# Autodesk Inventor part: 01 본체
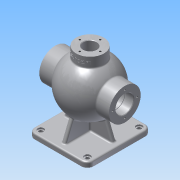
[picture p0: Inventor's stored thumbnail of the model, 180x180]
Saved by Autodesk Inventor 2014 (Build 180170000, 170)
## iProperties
Created: 2017-01
Part Number: 01 본체
Material: Aluminum 6061
Document SubType Name: Modeling
Designer: ksu
Density: 2.71 g/cm^3
Appearance: Aluminum - Flat
Author: ksu
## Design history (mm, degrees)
sketch "Sketch1"
  geometry: L1 (0, 0)-(20.642, 0); L2 (99.745, 0)-(136, 0); L3 (0, 0)-(136, 0); L4 (0, 0)-(136, 0); L5 (136, 0)-(136, 31); L6 (0, 31)-(0, 0); L7 (136, 31)-(110.741, 31); L8 (25.012, 31)-(0, 31); A1 r 53 centre (67.876, -0.171) between (110.741, 31) and (25.012, 31)
  constraints: 16 end point, 3 horizontal, 3 parallel, 2 point on circle, 1 centre point, 1 collinear, 1 perpendicular
  dimensions: "d2" = 136 distance between parallel lines of L6 L5; "d40" = 31 distance between parallel lines of L1 L8; "d41" = 31 distance between parallel lines of L2 L7
revolve "Revolution1" sketch "Sketch1" stored, may be unused: angle "d3" = 90 deg
workplane "Work Plane1"
sketch "Sketch2"
  geometry: L1 (0, 31)-(0, -31) reference; L2 (-136, 31)-(-136, -31) reference; L3 (-110.741, 31)-(-136, 31) reference; L4 (-22.5, 62.5)-(-113.5, 62.5); L5 (-125.5, 50.5)-(-125.5, -50.5); L6 (-113.5, -62.5)-(-22.5, -62.5); L7 (-10.5, -50.5)-(-10.5, 50.5); A1 r 12 centre (-22.5, 50.5) between (-10.5, 50.5) and (-22.5, 62.5); A2 r 12 centre (-22.5, -50.5) between (-22.5, -62.5) and (-10.5, -50.5); A3 r 12 centre (-113.5, -50.5) between (-125.5, -50.5) and (-113.5, -62.5); A4 r 12 centre (-113.5, 50.5) between (-113.5, 62.5) and (-125.5, 50.5); 4 further points
  constraints: 8 end point, 8 point on circle, 8 tangent, 6 point on line, 4 centre point, 3 equal radius, 2 parallel, 1 horizontal, 1 perpendicular
  dimensions: "d10" = 115 distance of point (-10.5, -62.5) point (-125.5, -62.5); "d11" = 125 distance of point (-125.5, -62.5) point (-125.5, 62.5); "d12" = 12 radius of A1
extrude "Extrusion1" join sketch "Sketch2" distance "d13" = 10; taper "d14" = 0 deg
sketch "Sketch3"
  geometry: A1 r 12 centre (113.5, -50.5) between (113.5, -62.5) and (125.5, -50.5) reference; A2 r 12 centre (113.5, 50.5) between (125.5, 50.5) and (113.5, 62.5) reference; A3 r 12 centre (22.5, 50.5) between (22.5, 62.5) and (10.5, 50.5) reference; A4 r 12 centre (22.5, -50.5) between (10.5, -50.5) and (22.5, -62.5) reference; 5 further points
  constraints: 4 coincident
hole "Hole1" sketch "Sketch3" at (22.5, -50.5), (22.5, 50.5), (113.5, 50.5), (113.5, -50.5) diameter "d15" = 8; stored, may be unused: countersink angle "d19" = 90 deg, drill point angle "d21" = 0 deg; dims "d16" = 6, "d17" = 12, "d18" = 3, "d20" = 10
workplane "Work Plane2"
workplane "Work Plane3"
workplane "Work Plane4"
sketch "Sketch10"
  geometry: C1 r 27 at (-67.876, -0.171); A1 r 53 centre (-67.876, -0.171) between (-25.012, 31) and (-110.741, 31) reference; 1 further point
  constraints: 1 centre point, 1 coincident
  dimensions: "d72" = 54 diameter of C1
extrude "Extrusion5" join sketch "Sketch10" distance "d73" = 50; taper "d74" = 0 deg
sketch "Sketch11"
  geometry: L1 (0, -31)-(0, 31) reference; L2 (0, 31)-(25.012, 31) reference; L3 (40.877, 45.436)-(40.877, 65) reference; L4 (40.877, 65)-(94.876, 65) reference; L5 (94.876, 65)-(94.876, 45.436) reference; L6 (110.741, 31)-(136, 31) reference; L7 (136, 31)-(136, -31) reference; L8 (136, -31)-(110.741, -31) reference; L9 (25.012, -31)-(0, -31) reference; L10 (10.5, -75)-(125.5, -75) reference; L11 (125.5, -75)-(125.5, -85) reference; L12 (125.5, -85)-(10.5, -85) reference; L13 (10.5, -85)-(10.5, -75) reference; L14 (0, 0)-(136, 0); L15 (136, 0)-(136, 17.5); L16 (0, 17.5)-(0, 0); L17 (28.523, 17.5)-(0, 17.5); L18 (120, 0)-(118.25, 0); L19 (118.25, 17.5)-(118.25, 18.5); L20 (118.25, 18.5)-(120, 18.5); L21 (120, 18.5)-(120, 17.5); L22 (136, 17.5)-(120, 17.5); L23 (118.25, 17.5)-(107.23, 17.5); A1 r 53 centre (67.876, -0.171) between (40.877, 45.436) and (25.012, 31) reference; A2 r 53 centre (67.876, -0.171) between (110.741, 31) and (94.876, 45.436) reference; A3 r 43 centre (67.876, 0.171) between (107.23, 17.5) and (28.523, 17.5); A4 r 53 centre (67.876, 0.171) between (25.012, -31) and (110.741, -31) reference
  constraints: 20 end point, 6 parallel, 2 horizontal, 2 perpendicular, 2 point on circle, 2 point on line, 1 centre point
  dimensions: "d75" = 86 diameter of A3; "d77" = 1.75 distance of L19.end L20.end; "d78" = 16 distance between parallel lines of L7 L21; "d79" = 18.5 distance of L20.end L18.start
revolve "Revolution2" sketch "Sketch11" stored, may be unused: angle "d80" = 90 deg
sketch "Sketch12"
  geometry: C1 r 17.5 at (0, 0) reference; 4 further points
  constraints: 5 other
  dimensions: "d81" = 24 distance of C1.centre point (0, 24); "d84" = 360 deg dimension on C1.centre point (0, 24) (derived)
hole "Hole2" sketch "Sketch12" at (0, 24), (-24, 0), (0, -24), (24, 0) diameter "d86" = 3.459; stored, may be unused: countersink angle "d90" = 90 deg, drill point angle "d92" = 118 deg; dims "d87" = 16, "d88" = 12, "d89" = 3, "d91" = 19
sketch "Sketch13"
  geometry: C1 r 17.5 at (0, 0) reference; 4 further points
  constraints: 5 other
  dimensions: "d93" = 22.5 distance of C1.centre point (0, 22.5); "d96" = 360 deg dimension on C1.centre point (0, 22.5) (derived)
hole "Hole3" sketch "Sketch13" at (0, 22.5), (-22.5, 0), (0, -22.5), (22.5, 0) diameter "d98" = 3.459; stored, may be unused: countersink angle "d102" = 90 deg, drill point angle "d104" = 118 deg; dims "d99" = 12, "d100" = 12, "d101" = 3, "d103" = 15
sketch "Sketch14"
  geometry: C1 r 27 at (0, 0) reference; C2 r 13 at (0, 0); 1 further point
  constraints: 1 centre point, 1 coincident
  dimensions: "d105" = 26 diameter of C2
extrude "Extrusion6" cut sketch "Sketch14" distance "d106" = 50; taper "d107" = 0 deg
sketch "Sketch15"
  geometry: C1 r 13 at (0, 0) reference; 5 further points
  constraints: 5 other
  dimensions: "d108" = 20 distance of C1.centre point (0, 20); "d111" = 360 deg dimension on C1.centre point (0, 20) (derived)
hole "Hole4" sketch "Sketch15" at (0, 20), (-20, 0), (0, -20), (20, 0) diameter "d113" = 3.459; stored, may be unused: countersink angle "d117" = 90 deg, drill point angle "d119" = 118 deg; dims "d114" = 9, "d115" = 12, "d116" = 3, "d118" = 11
chamfer "Chamfer1" distance "d120" = 1; stored, may be unused: second distance "d121" = 2, angle "d122" = 45 deg
fillet "Fillet1" dims "d123" = 3
fillet "Fillet3" dims "d125" = 3
sketch "Sketch16"
  geometry: L1 (16.039, 22.5)-(15, 24.23) reference; L2 (15, 24.23)-(0, 24.23) reference; L3 (0, 24.23)-(0, 31) reference; L4 (0, 31)-(23.51, 31) reference; L5 (40.877, 47.116)-(40.877, 65) reference; L6 (40.877, 65)-(46.155, 65) reference; L7 (46.155, 65)-(46.155, 54) reference; L8 (49.597, 54)-(49.597, 65) reference; L9 (49.597, 65)-(53.877, 65) reference; L10 (53.877, 65)-(54.877, 64) reference; L11 (54.877, 64)-(54.877, 41.159) reference; L12 (28.523, 17.5)-(1, 17.5) reference; L13 (1, 17.5)-(0, 18.5) reference; L14 (0, 18.5)-(0, 20.77) reference; L15 (0, 20.77)-(15, 20.77) reference; L16 (15, 20.77)-(16.039, 22.5) reference; L17 (117, -22.271)-(115.961, -24) reference; L18 (115.961, -24)-(117, -25.73) reference; L19 (117, -25.73)-(136, -25.73) reference; L20 (136, -25.73)-(136, -31) reference; L21 (136, -31)-(112.242, -31) reference; L22 (23.51, -31)-(0, -31) reference; L23 (0, -31)-(0, -24.23) reference; L24 (0, -24.23)-(15, -24.23) reference; L25 (15, -24.23)-(16.039, -22.5) reference; L26 (16.039, -22.5)-(15, -20.77) reference; L27 (15, -20.77)-(0, -20.77) reference; L28 (0, -20.77)-(0, -18.5) reference; L29 (0, -18.5)-(1, -17.5) reference; L30 (1, -17.5)-(28.523, -17.5) reference; L31 (107.23, -17.5)-(118.25, -17.5) reference; L32 (118.25, -17.5)-(118.25, -18.5) reference; L33 (118.25, -18.5)-(120, -18.5) reference; L34 (120, -18.5)-(120, -17.5) reference; L35 (120, -17.5)-(135, -17.5) reference; L36 (135, -17.5)-(136, -18.5) reference; L37 (136, -18.5)-(136, -22.271) reference; L38 (136, -22.271)-(117, -22.271) reference; L39 (117, 25.73)-(115.961, 24) reference; L40 (115.961, 24)-(117, 22.271) reference; L41 (117, 22.271)-(136, 22.271) reference; L42 (136, 22.271)-(136, 18.5) reference; L43 (136, 18.5)-(135, 17.5) reference; L44 (135, 17.5)-(120, 17.5) reference; L45 (120, 17.5)-(120, 18.5) reference; L46 (120, 18.5)-(118.25, 18.5) reference; L47 (118.25, 18.5)-(118.25, 17.5) reference; L48 (118.25, 17.5)-(107.23, 17.5) reference; L49 (80.875, 41.159)-(80.875, 64) reference; L50 (80.875, 64)-(81.875, 65) reference; L51 (81.875, 65)-(86.155, 65) reference; L52 (86.155, 65)-(86.155, 54) reference; L53 (89.597, 54)-(89.597, 65) reference; L54 (89.597, 65)-(94.876, 65) reference; L55 (94.876, 65)-(94.876, 47.116) reference; L56 (112.242, 31)-(136, 31) reference; L57 (136, 31)-(136, 25.73) reference; L58 (136, 25.73)-(117, 25.73) reference; L59 (125.5, -78)-(125.5, -85) reference; L60 (125.5, -85)-(10.5, -85) reference; L61 (10.5, -85)-(10.5, -78) reference; L62 (13.5, -75)-(122.5, -75) reference; L63 (20.5, -75)-(36.603, -35.143); L64 (115.5, -75)-(99.331, -34.98)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; A1 r 3 centre (23.51, 34) between (23.51, 31) and (25.887, 32.169) reference; A2 r 53 centre (67.876, -0.171) between (39.484, 44.583) and (25.887, 32.169) reference; A3 r 43 centre (67.876, 0.171) between (54.877, 41.159) and (28.523, 17.5) reference; A4 r 3 centre (112.242, -34) between (112.242, -31) and (109.866, -32.169) reference; A5 r 53 centre (67.876, 0.171) between (25.887, -32.169) and (109.866, -32.169) reference; A6 r 3 centre (23.51, -34) between (25.887, -32.169) and (23.51, -31) reference; A7 r 43 centre (67.876, -0.171) between (28.523, -17.5) and (107.23, -17.5) reference; A8 r 43 centre (67.876, 0.171) between (107.23, 17.5) and (80.875, 41.159) reference; A9 r 53 centre (67.876, -0.171) between (109.866, 32.169) and (96.269, 44.583) reference; A10 r 3 centre (112.242, 34) between (109.866, 32.169) and (112.242, 31) reference; A11 r 3 centre (122.5, -78) between (125.5, -78) and (122.5, -75) reference; A12 r 3 centre (13.5, -78) between (13.5, -75) and (10.5, -78) reference; A13 r 46.916 centre (67.876, -0.171) between (36.603, -35.143) and (99.331, -34.98); 1 further point
  constraints: 6 end point, 2 horizontal alignment, 2 point on circle, 2 point on line, 1 centre point, 1 coincident, 1 collinear, 2 other
  dimensions: "d126" = 22 deg angle of L61 L63; "d127" = 22 deg angle of L59 L64; "d128" = 10 distance from line of L59 L64.start; "d129" = 10 distance from line of L61 L63.start
extrude "Extrusion7" join sketch "Sketch16" distance "d130" = 4; taper "d132" = 0 deg; dims "d131" = 4, "d133" = 0
workplane "Work Plane5"
sketch "Sketch17"
  geometry: L1 (54, -21.896)-(65, -21.896) reference; L2 (65, -21.896)-(65, -27.171) reference; L3 (65, -27.171)-(46.975, -27.171) reference; L4 (-52.677, -4)-(-75, -4) reference; L5 (-75, -4)-(-75, -59.5) reference; L6 (-78, -62.5)-(-85, -62.5) reference; L7 (-85, -62.5)-(-85, 62.5) reference; L8 (-85, 62.5)-(-78, 62.5) reference; L9 (-75, 59.5)-(-75, 4) reference; L10 (-75, 4)-(-52.677, 4) reference; L11 (47.192, 26.829)-(65, 26.829) reference; L12 (65, 26.829)-(65, 21.554) reference; L13 (65, 21.554)-(54, 21.554) reference; L14 (54, 18.104)-(65, 18.104) reference; L15 (65, 18.104)-(65, 13.829) reference; L16 (65, 13.829)-(64, 12.829) reference; L17 (64, 12.829)-(41.221, 12.829) reference; L18 (41.113, -13.17)-(64, -13.17) reference; L19 (64, -13.17)-(65, -14.17) reference; L20 (65, -14.17)-(65, -18.446) reference; L21 (65, -18.446)-(54, -18.446) reference; L22 (-75, 52.5)-(-32.266, 35.234); L23 (-75, -52.5)-(-32.266, -35.234); L24 (-75, 52.5)-(-75, -52.5); A1 r 52.829 centre (0, 0) between (-52.677, -4) and (44.45, -28.549) reference; A2 r 3 centre (-78, -59.5) between (-78, -62.5) and (-75, -59.5) reference; A3 r 3 centre (-78, 59.5) between (-75, 59.5) and (-78, 62.5) reference; A4 r 52.829 centre (0, 0) between (44.656, 28.226) and (-52.677, 4) reference; A5 r 43.171 centre (0, 0) between (41.221, 12.829) and (41.113, -13.17) reference; A6 r 47.776 centre (0, 0) between (-32.266, 35.234) and (-32.266, -35.234); 1 further point
  constraints: 6 end point, 2 point on circle, 2 point on line, 2 vertical alignment, 1 centre point, 1 coincident, 1 perpendicular, 2 other
  dimensions: "d135" = 22 deg angle of L23 L6; "d136" = 10 distance from line of L6 L23.start; "d137" = 22 deg angle of L8 L22; "d138" = 10 distance from line of L8 L22.start
extrude "Extrusion8" join sketch "Sketch17" distance "d139" = 4; taper "d141" = 0 deg; dims "d140" = 4, "d142" = 0
fillet "Fillet4" dims "d143" = 3
workplane "Work Plane6"
workplane "Work Plane7"
sketch "Sketch19"
  geometry: L1 (40.876, 65)-(94.876, 65) reference; L2 (40.876, 65)-(40.876, 47.115) reference; L3 (-88.616, 58.002)-(224.368, 58.002); L4 (224.368, 58.002)-(224.368, 51.998); L5 (224.368, 51.998)-(-88.616, 51.998); L6 (-88.616, 51.998)-(-88.616, 58.002); L7 (224.368, 55)-(-88.616, 55); L8 (67.876, 58.002)-(67.876, 51.998); 1 further point
  constraints: 4 end point, 4 midpoint, 2 other
  dimensions: "d148" = 27 distance between parallel lines of L2 L8; "d149" = 10 distance between parallel lines of L1 L7
emboss "Emboss1" sketch "Sketch19" dims "d10" = 115, "d11" = 125, "d12" = 12, "d150" = 0.5, "d151" = 0
body "Solid1"
node "Project Cut Edges7"
node "Project Cut Edges8"
node "Project Cut Edges9"
other parameters: "d4" = -85, "d22" = 68, "d42" = 68, "d71" = 65, "d76" = 17.5, "d134" = 68, "d144" = -27, "d147" = 27
